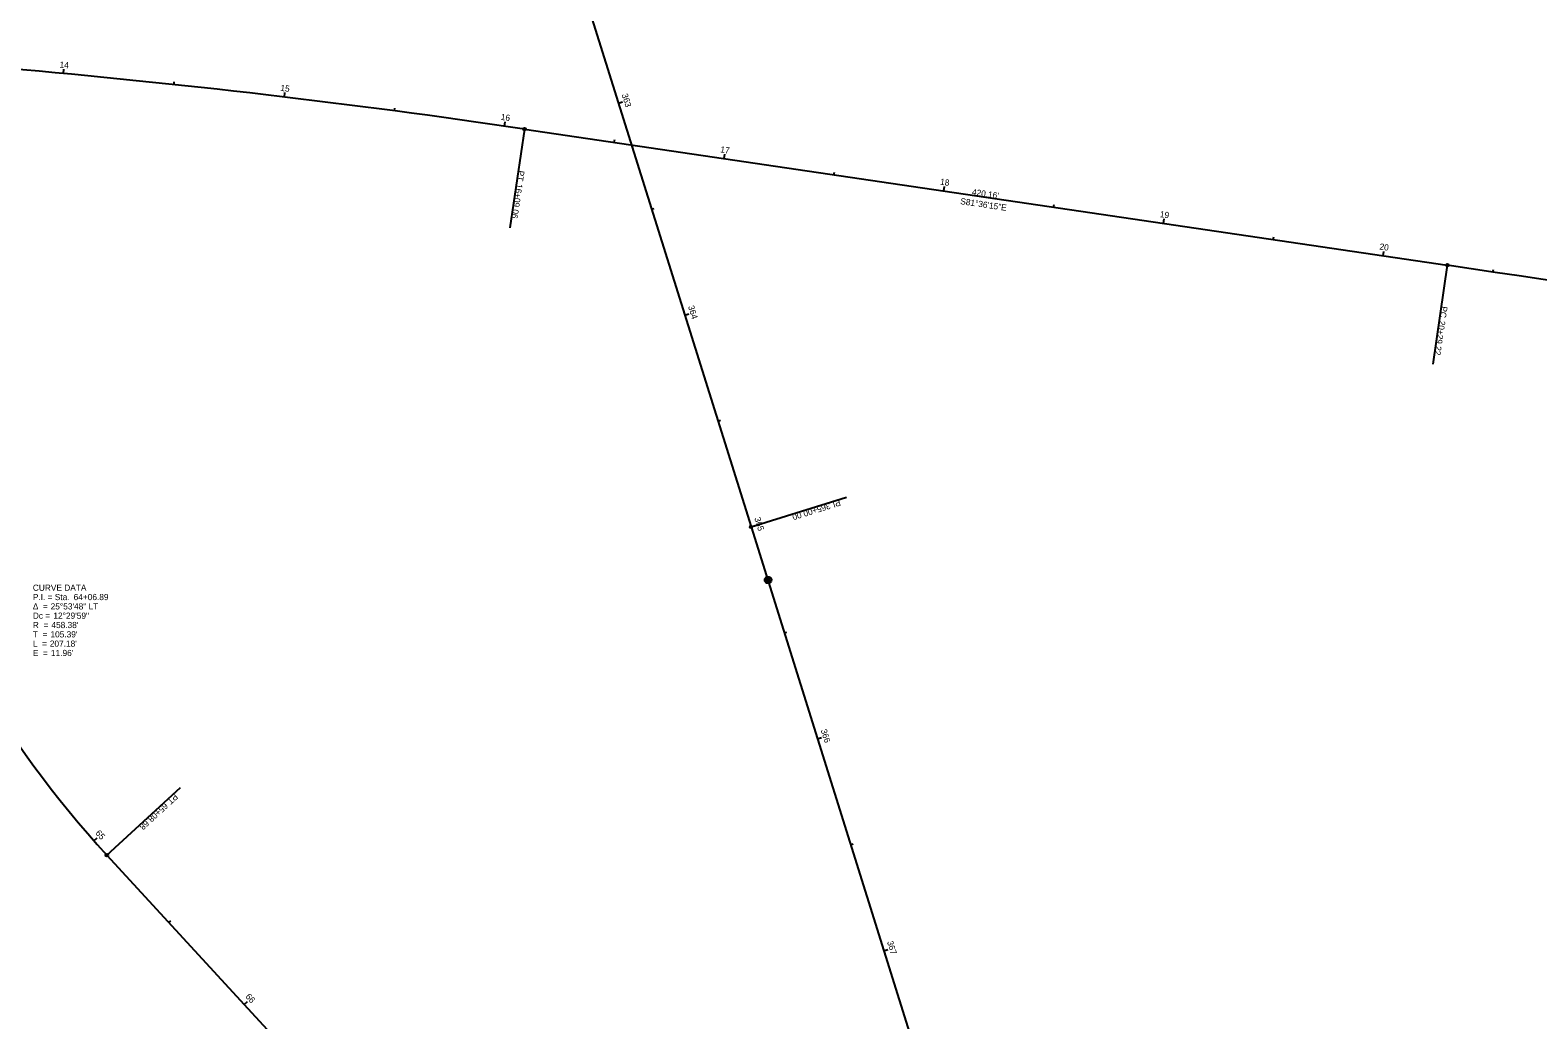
# Model space of a CAD drawing. Extents: x 1918148 to 1920349, y 624677 to 627727.
# Drawn here: x 1918991 to 1919670, y 625435 to 625880 of the extents above; entities that cross this region are included whole.
import ezdxf

# ---------------------------------------------------------------- set-up
doc = ezdxf.new("R2010")
doc.units = 0
for name, color, linetype in [('_CIVIL_CONSTRUCTION', 7, 'Continuous'), ('RS_Raster1', 7, 'Continuous'), ('RW_X_CL', 7, 'Continuous'), ('RW_X_CL_100_Bearings', 7, 'Continuous'), ('RW_X_CL_100_Cardinal_Points', 7, 'Continuous'), ('RW_X_CL_100_Curve_Data', 7, 'Continuous'), ('SV_X_Mon_Cells_Found', 7, 'Continuous')]:
    doc.layers.add(name, color=color, linetype=linetype)

msp = doc.modelspace()

# ---------------------------------------------------------------- linework, layer by layer
at = {"layer": 'RS_Raster1'}
for p, q in [((1919166.18, 626133.77), (1919315.59, 625656.61)), ((1919213.52, 625835.85), (1919629.17, 625774.5)), ((1919315.59, 625656.61), (1919465, 625179.46)), ((1919025.5, 625508.81), (1919254.38, 625259.79))]:
    msp.add_line(p, q, dxfattribs=at)
for centre, radius, start, end in [((1918643.12, 621971.22), 3906.49, 81.60417, 88.49278), ((1917955.99, 614438.02), 11459.29, 79.859722, 81.604167), ((1919362.98, 625819), 458.38, 196.69, 222.58667)]:
    msp.add_arc(centre, radius, start, end, dxfattribs=at)
at = {"layer": 'RW_X_CL'}
for p, q in [((1919213.52, 625835.85), (1919206.95, 625791.33)), ((1919629.17, 625774.5), (1919622.6, 625729.98)), ((1919315.59, 625656.61), (1919358.54, 625670.06)), ((1919025.5, 625508.81), (1919058.63, 625539.26))]:
    msp.add_line(p, q, dxfattribs=at)
for centre in [(1919213.52, 625835.85), (1919629.17, 625774.5), (1919315.59, 625656.61), (1919025.5, 625508.81)]:
    msp.add_circle(centre, 0.6, dxfattribs=at)
at = {"layer": 'RW_X_CL_100_Cardinal_Points'}
for p, q in [((1919005.97, 625860.83), (1919006.16, 625862.82)), ((1919055.73, 625855.86), (1919055.85, 625857.06)), ((1919105.41, 625850.27), (1919105.65, 625852.25)), ((1919155.02, 625844.03), (1919155.18, 625845.22)), ((1919255.83, 625847.48), (1919257.73, 625848.07)), ((1919204.55, 625837.16), (1919204.84, 625839.14)), ((1919254.01, 625829.87), (1919254.19, 625831.06)), ((1919303.48, 625822.57), (1919303.77, 625824.55)), ((1919352.94, 625815.27), (1919353.12, 625816.46)), ((1919402.41, 625807.97), (1919402.7, 625809.95)), ((1919451.87, 625800.67), (1919452.05, 625801.86)), ((1919270.77, 625799.76), (1919271.91, 625800.12)), ((1919501.33, 625793.37), (1919501.63, 625795.35)), ((1919550.8, 625786.07), (1919550.97, 625787.26)), ((1919600.26, 625778.77), (1919600.55, 625780.75)), ((1919649.72, 625771.45), (1919649.9, 625772.64)), ((1919285.71, 625752.04), (1919287.62, 625752.64)), ((1919300.65, 625704.33), (1919301.8, 625704.69)), ((1919315.59, 625656.61), (1919317.5, 625657.21)), ((1919330.53, 625608.9), (1919331.68, 625609.26)), ((1919345.47, 625561.18), (1919347.38, 625561.78)), ((1919019.68, 625515.26), (1919021.18, 625516.58)), ((1919360.41, 625513.47), (1919361.56, 625513.83)), ((1919053.46, 625478.39), (1919054.34, 625479.2)), ((1919375.36, 625465.75), (1919377.26, 625466.35)), ((1919087.29, 625441.58), (1919088.77, 625442.93))]:
    msp.add_line(p, q, dxfattribs=at)
at = {"layer": 'SV_X_Mon_Cells_Found'}
for radius in [1.5, 0.8]:
    msp.add_circle((1919323.24, 625632.72), radius, dxfattribs=at)

# ---------------------------------------------------------------- texts
at = {"layer": '_CIVIL_CONSTRUCTION'}
msp.add_text('S81°36\'15"E', height=2.8, rotation=351.60417, dxfattribs=at).set_placement((1919409.69, 625802.04))
at = {"layer": 'RW_X_CL'}
for s, rotation, p in [('PT', 261.60417, (1919210.83, 625817.32)), ('16+09.06', 261.60417, (1919209.94, 625811.3)), ('PC', 261.60417, (1919626.52, 625756.17)), ('20+29.22', 261.60417, (1919625.56, 625749.72)), ('365+00.00', 197.38701, (1919350.84, 625667.6)), ('PI', 197.38701, (1919355.41, 625669.03)), ('65+08.68', 222.58667, (1919051.43, 625532.59)), ('PT', 222.58667, (1919055.91, 625536.7))]:
    msp.add_text(s, height=2.8, rotation=rotation, dxfattribs=at).set_placement(p)
at = {"layer": 'RW_X_CL_100_Bearings'}
for s, p in [('CURVE DATA', (1918992.14, 625627.85)), ('P.I. = Sta. ', (1918992.14, 625623.65)), ('64+06.89', (1919010.51, 625623.65)), ('Δ  = ', (1918992.14, 625619.45)), ('25°53\'48" LT', (1919000.16, 625619.45)), ('Dc = ', (1918992.14, 625615.25)), ('R  = ', (1918992.14, 625611.05)), ("458.38'", (1919000.5, 625611.05)), ('12°29\'59"', (1919001.38, 625615.25)), ('T  = ', (1918992.14, 625606.85)), ('L  = ', (1918992.14, 625602.65)), ("207.18'", (1918999.78, 625602.65)), ("105.39'", (1919000.07, 625606.85)), ('E  = ', (1918992.14, 625598.45)), ("11.96'", (1919000.29, 625598.45))]:
    msp.add_text(s, height=2.8, dxfattribs=at).set_placement(p)
at = {"layer": 'RW_X_CL_100_Cardinal_Points'}
for s, rotation, p in [('14', 354.67046, (1919004.07, 625863.52)), ('15', 353.20378, (1919103.52, 625853.06)), ('363', 287.38701, (1919257.28, 625851.35)), ('16', 351.7371, (1919202.74, 625840)), ('17', 351.60417, (1919301.62, 625825.37)), ('18', 351.60417, (1919400.61, 625810.81)), ('19', 351.60417, (1919499.56, 625796.2)), ('20', 351.60417, (1919598.46, 625781.61)), ('364', 287.38701, (1919287.17, 625755.9)), ('365', 287.38701, (1919317.04, 625660.52)), ('366', 287.38701, (1919346.92, 625565.08)), ('65', 311.50177, (1919020.13, 625518.6)), ('367', 287.38701, (1919376.79, 625469.7)), ('66', 312.58667, (1919087.68, 625444.92))]:
    msp.add_text(s, height=2.8, rotation=rotation, dxfattribs=at).set_placement(p)
at = {"layer": 'RW_X_CL_100_Curve_Data'}
msp.add_text("420.16'", height=2.8, rotation=351.60417, dxfattribs=at).set_placement((1919414.93, 625806.17))

doc.saveas('drawing.dxf')
